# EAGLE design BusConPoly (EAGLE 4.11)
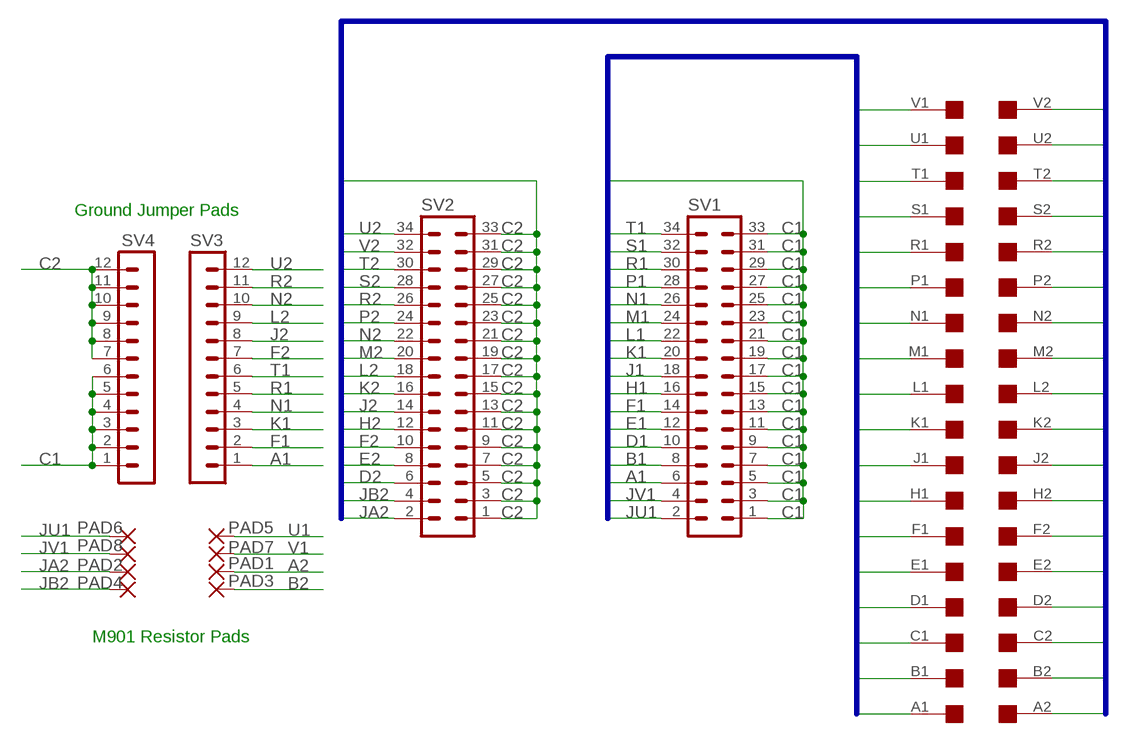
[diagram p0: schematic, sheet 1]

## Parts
PAD1  1,6/0,8  [1,6/0,8]
PAD2  1,6/0,8  [1,6/0,8]
PAD3  1,6/0,8  [1,6/0,8]
PAD4  1,6/0,8  [1,6/0,8]
PAD5  1,6/0,8  [1,6/0,8]
PAD6  1,6/0,8  [1,6/0,8]
PAD7  1,6/0,8  [1,6/0,8]
PAD8  1,6/0,8  [1,6/0,8]
SV1  MA17-2  [MA17-2]
SV2  MA17-2  [MA17-2]
SV3  MA12-1  [MA12-1]
SV4  MA12-1  [MA12-1]
U$4  EDGE-2  [EDGE-CON2]

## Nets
A1: SV1.6 SV3.1 U$4.A1
A2: PAD1.1(P) U$4.A2
B1: SV1.8 U$4.B1
B2: PAD3.1(P) U$4.B2
C1: SV1.1 SV1.3 SV1.5 SV1.7 SV1.9 SV1.11 SV1.13 SV1.15 SV1.17 SV1.19 SV1.21 SV1.23 SV1.25 SV1.27 SV1.29 SV1.31 SV1.33 SV4.1 SV4.2 SV4.3 SV4.4 SV4.5 SV4.6 U$4.C1
C2: SV2.1 SV2.3 SV2.5 SV2.7 SV2.9 SV2.11 SV2.13 SV2.15 SV2.17 SV2.19 SV2.21 SV2.23 SV2.25 SV2.27 SV2.29 SV2.31 SV2.33 SV4.7 SV4.8 SV4.9 SV4.10 SV4.11 SV4.12 U$4.C2
D1: SV1.10 U$4.D1
D2: SV2.6 U$4.D2
E1: SV1.12 U$4.E1
E2: SV2.8 U$4.E2
F1: SV1.14 SV3.2 U$4.F1
F2: SV2.10 SV3.7 U$4.F2
H1: SV1.16 U$4.H1
H2: SV2.12 U$4.H2
J1: SV1.18 U$4.J1
J2: SV2.14 SV3.8 U$4.J2
JA2: PAD2.1(P) SV2.2
JB2: PAD4.1(P) SV2.4
JU1: PAD6.1(P) SV1.2
JV1: PAD8.1(P) SV1.4
K1: SV1.20 SV3.3 U$4.K1
K2: SV2.16 U$4.K2
L1: SV1.22 U$4.L1
L2: SV2.18 SV3.9 U$4.L2
M1: SV1.24 U$4.M1
M2: SV2.20 U$4.M2
N1: SV1.26 SV3.4 U$4.N1
N2: SV2.22 SV3.10 U$4.N2
P1: SV1.28 U$4.P1
P2: SV2.24 U$4.P2
R1: SV1.30 SV3.5 U$4.R1
R2: SV2.26 SV3.11 U$4.R2
S1: SV1.32 U$4.S1
S2: SV2.28 U$4.S2
T1: SV1.34 SV3.6 U$4.T1
T2: SV2.30 U$4.T2
U1: PAD5.1(P) U$4.U1
U2: SV2.34 SV3.12 U$4.U2
V1: PAD7.1(P) U$4.V1
V2: SV2.32 U$4.V2

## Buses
A1,B1,C1,D1,E1,F1,H1,J1,K1,L1,M1,N1,P1,R1,S1,T1,U1,V1
A2,B2,C2,D2,E2,F2,H2,J2,K2,L2,M2,N2,P2,R2,S2,T2,U2,V2

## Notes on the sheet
- Ground Jumper Pads
- M901 Resistor Pads

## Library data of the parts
PAD1-PAD8 = wirepad:1,6/0,8: THROUGH-HOLE PAD
SV1 SV2 = con-lstb:MA17-2: PIN HEADER
SV3 SV4 = con-lstb:MA12-1: PIN HEADER
U$4 = dec-con:EDGE-2: Double-Sided DEC edge connector.

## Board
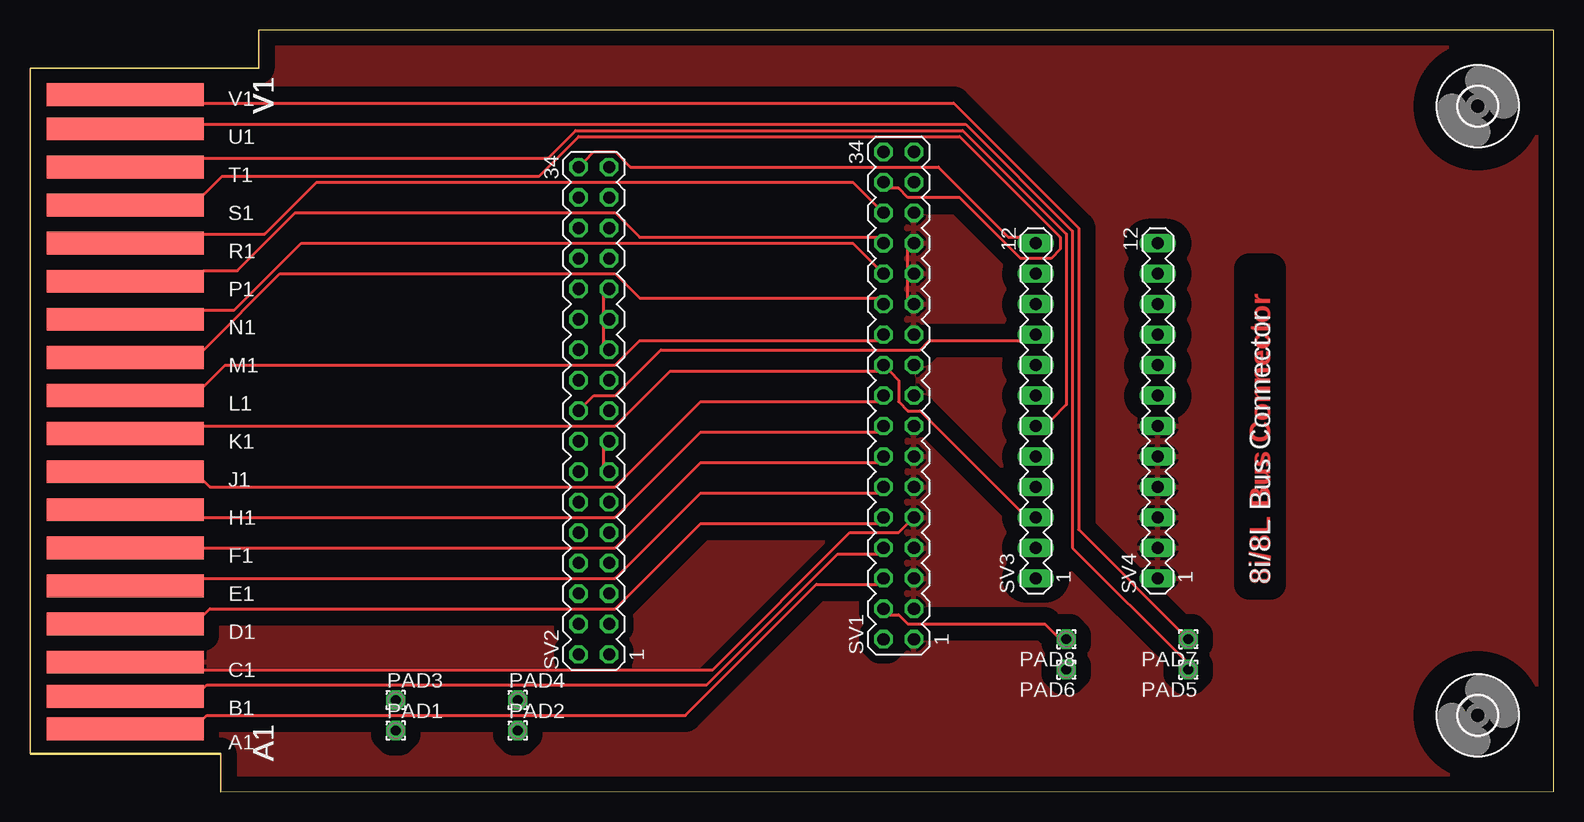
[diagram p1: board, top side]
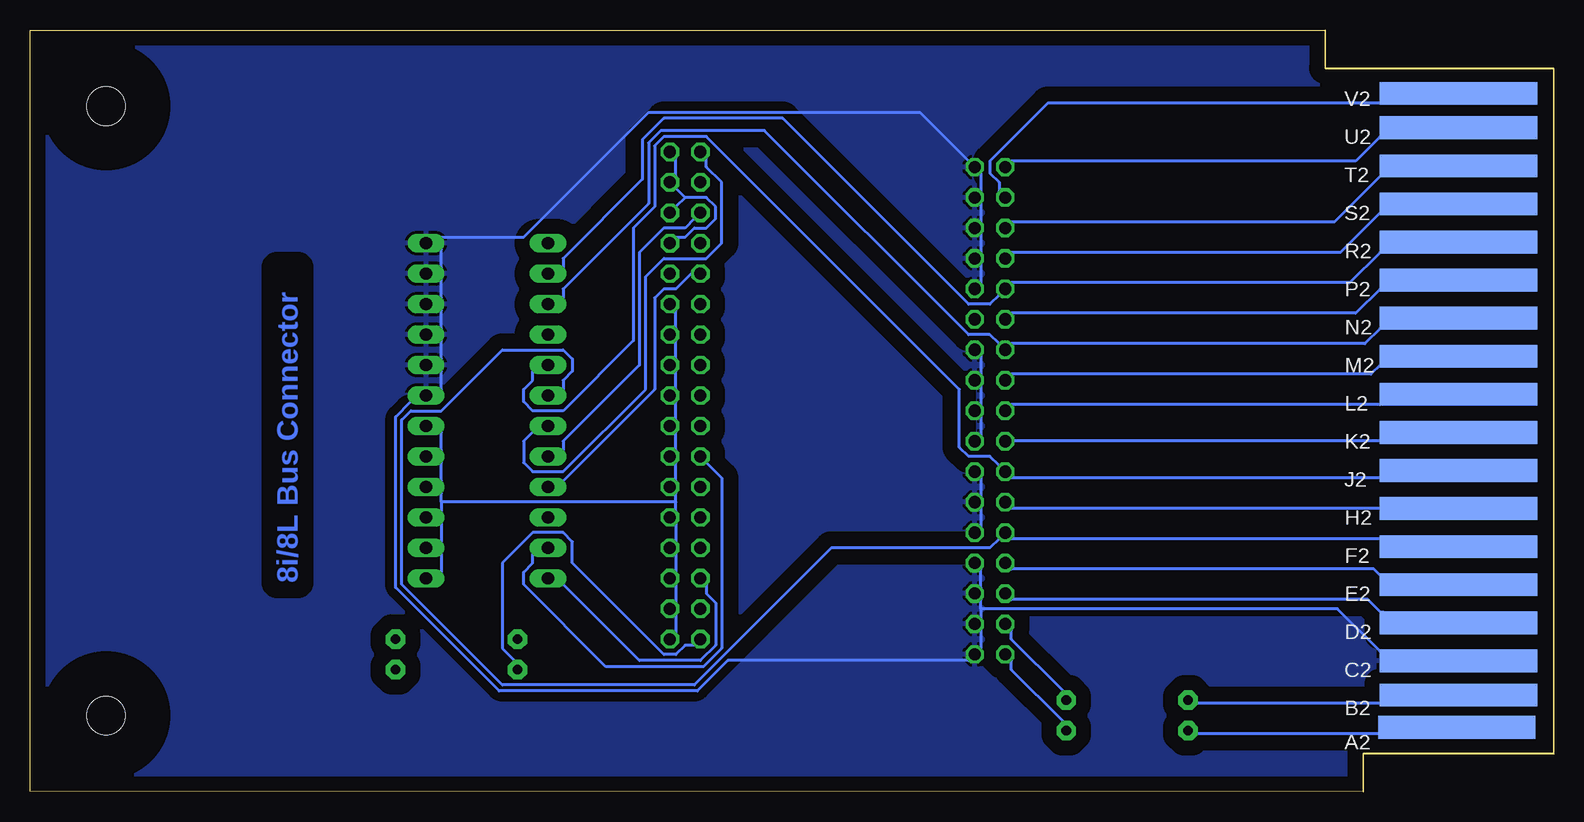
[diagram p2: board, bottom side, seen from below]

Size 126.98 x 63.5 mm. Coordinates in mm from the lower left corner, seen from the top.
Outline: 0.01,3.09 15.88,3.09 15.88,0 126.98,0.04 126.98,63.46 19.05,63.5 19.05,60.29 0.01,60.29 0.01,3.09
Copper layers (1*16): Top 0.035mm / dielectric 1.5mm / Bottom 0.035mm
Design rules "olimex10mil": minimum track width 10mil, minimum drill 24mil, track to track 10mil, track to pad 10mil, pad to pad 10mil, via to via 10mil, smd to smd 10mil, copper to edge 40mil, drill to drill 10mil, minimum pad ring 10mil, minimum via ring 8mil, stop-mask expansion 0mil, vias tented up to drill 0mil, thermal gap 10mil

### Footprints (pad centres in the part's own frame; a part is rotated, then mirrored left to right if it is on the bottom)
1,6/0,8 = drill 0.813 pad 1.6 octagon: 1 0,0
MA17-2 = drill 1.016 octagon: 1 -20.32,-1.27; 2 -20.32,1.27; 3 -17.78,-1.27; 4 -17.78,1.27; 5 -15.24,-1.27; 6 -15.24,1.27; 7 -12.7,-1.27; 8 -12.7,1.27; 9 -10.16,-1.27; 10 -10.16,1.27; 11 -7.62,-1.27; 12 -7.62,1.27; 13 -5.08,-1.27; 14 -5.08,1.27; 15 -2.54,-1.27; 16 -2.54,1.27; 17 0,-1.27; 18 0,1.27; 19 2.54,-1.27; 20 2.54,1.27; 21 5.08,-1.27; 22 5.08,1.27; 23 7.62,-1.27; 24 7.62,1.27; 25 10.16,-1.27; 26 10.16,1.27; 27 12.7,-1.27; 28 12.7,1.27; 29 15.24,-1.27; 30 15.24,1.27; 31 17.78,-1.27; 32 17.78,1.27; 33 20.32,-1.27; 34 20.32,1.27
MA12-1 = drill 1.016 long: 1 -13.97,0; 2 -11.43,0; 3 -8.89,0; 4 -6.35,0; 5 -3.81,0; 6 -1.27,0; 7 1.27,0; 8 3.81,0; 9 6.35,0; 10 8.89,0; 11 11.43,0; 12 13.97,0
3,2 = hole 3.2: 0,0
EDGE-CON2 = smd 13.106 x 1.905: A1 7.938,5.239; B1 7.938,7.938; C1 7.938,10.795; D1 7.938,13.97; E1 7.938,17.145; F1 7.938,20.32; H1 7.938,23.495; J1 7.938,26.67; K1 7.938,29.845; L1 7.938,33.02; M1 7.938,36.195; N1 7.938,39.37; P1 7.938,42.545; R1 7.938,45.72; S1 7.938,48.895; T1 7.938,52.07; U1 7.938,55.245; V1 7.938,58.102 | smd 13.106 x 1.905 bottom: A2 8.096,5.34; B2 7.938,8.039; C2 7.938,10.897; D2 7.938,14.072; E2 7.938,17.247; F2 7.938,20.422; H2 7.938,23.597; J2 7.938,26.772; K2 7.938,29.947; L2 7.938,33.122; M2 7.938,36.297; N2 7.938,39.472; P2 7.938,42.647; R2 7.938,45.822; S2 7.938,48.997; T2 7.938,52.172; U2 7.938,55.347; V2 7.938,58.204

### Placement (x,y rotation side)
PAD1  30.48,5.08 0 top
PAD2  40.64,5.08 0 top
PAD3  30.48,7.62 0 top
PAD4  40.64,7.62 0 top
PAD5  96.52,10.16 180 top
PAD6  86.36,10.16 180 top
PAD7  96.52,12.7 180 top
PAD8  86.36,12.7 180 top
SV1  72.39,33.02 90 top
SV2  46.99,31.75 90 top
SV3  83.82,31.75 90 top
SV4  93.98,31.75 90 top
U$2  [3,2]  120.65,6.35 0 top
U$3  [3,2]  120.65,57.15 0 top
U$4  0,0 0 top

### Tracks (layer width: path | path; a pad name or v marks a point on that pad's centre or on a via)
A1
  Top 0.254: SV1.6 70.61,17.27 65.53,17.27 54.61,6.35 14.73,6.35 14.48,6.1 U$4.A1
  Bottom 0.254: SV1.6 70.61,17.27 70.61,16.51 69.85,15.75 69.85,12.19 71.12,10.92 76.2,10.92 82.55,17.27 SV3.1
A2
  Bottom 0.254: PAD1.1 29.72,4.83 14.48,4.83 U$4.A2
B1
  Top 0.254: SV1.8 70.61,19.81 67.31,19.81 56.39,8.89 14.73,8.89 14.48,8.64 U$4.B1
B2
  Bottom 0.254: PAD3.1 29.72,7.37 14.48,7.37 U$4.B2
C1
  Top 0.254: SV1.23 73.15,41.15 73.15,42.67 SV1.25 73.15,43.69 73.15,45.21 SV1.27 | U$4.C1 14.48,10.16 56.9,10.16 68.33,21.59 72.39,21.59 73.15,22.35 SV1.9
  Bottom 0.254: SV4.1 92.71,18.29 92.71,19.81 SV4.2 92.71,20.83 92.71,22.35 SV4.3 92.71,23.37 92.71,24.13 | 92.71,24.13 92.71,24.89 SV4.4 92.71,25.91 92.71,27.43 SV4.5 92.71,28.45 92.71,29.97 SV4.6 | 72.39,49.53 70.61,49.53 69.85,48.77 69.85,47.75 70.61,46.99 71.63,46.99 72.39,46.23 73.15,46.23 SV1.27 | 72.39,49.53 73.15,50.29 SV1.31 73.15,51.31 73.15,52.83 SV1.33 | 72.39,49.53 73.15,48.77 SV1.29 | SV1.1 73.15,13.21 73.15,14.73 SV1.3 73.15,15.75 73.15,17.27 SV1.5 73.15,18.29 73.15,19.81 SV1.7 73.15,20.83 73.15,22.35 SV1.9 73.15,23.37 73.15,24.13 | 73.15,24.13 73.15,24.89 SV1.11 73.15,25.91 73.15,27.43 SV1.13 73.15,28.45 73.15,29.97 SV1.15 73.15,30.99 73.15,32.51 SV1.17 73.15,33.53 73.15,35.05 SV1.19 73.15,36.07 73.15,37.59 SV1.21 73.15,38.61 73.15,40.13 SV1.23 | 73.15,24.13 92.71,24.13
  pour Top (isolate 1.27): 0,59.69 19.05,59.69 19.05,63.5 127,63.5 127,0 16.51,0 16.51,2.54 16.51,3.81 0,3.81
C2
  Top 0.254: SV2.21 47.75,37.34 47.75,38.86 SV2.23 47.75,39.88 47.75,41.4 SV2.25 | SV2.13 47.75,27.18 47.75,28.7 SV2.15
  Bottom 0.254: 47.75,15.24 47.75,14.48 SV2.3 47.75,13.46 47.75,11.94 SV2.1 48.77,10.92 68.83,10.92 71.37,8.38 87.88,8.38 96.52,17.02 96.52,31.24 95.25,32.51 SV4.7 92.71,33.53 92.71,35.05 SV4.8 92.71,36.07 92.71,37.59 SV4.9 92.71,38.61 92.71,40.13 SV4.10 92.71,41.15 92.71,42.67 SV4.11 92.71,43.69 92.71,45.21 SV4.12 92.71,46.23 85.85,46.23 75.44,56.64 52.83,56.64 48.77,52.58 SV2.33 47.75,51.56 47.75,50.04 SV2.31 47.75,49.02 47.75,47.5 SV2.29 47.75,46.48 47.75,44.96 SV2.27 47.75,43.94 47.75,42.42 SV2.25 | 47.75,15.24 47.75,16 SV2.5 47.75,17.02 47.75,18.54 SV2.7 | 47.75,15.24 18.03,15.24 14.48,11.68 U$4.C2 | SV2.9 47.75,22.1 47.75,23.62 SV2.11 47.75,24.64 47.75,26.16 SV2.13 | SV2.15 47.75,29.72 47.75,31.24 SV2.17 47.75,32.26 47.75,33.78 SV2.19 47.75,34.8 47.75,36.32 SV2.21
  pour Bottom (isolate 1.27): 0,59.69 19.05,59.69 19.05,63.5 127,63.5 127,0 16.51,0 16.51,2.54 16.51,3.81 0,3.81
D1
  Top 0.254: SV1.10 70.61,22.35 55.88,22.35 48.77,15.24 14.99,15.24 14.48,14.73 U$4.D1
D2
  Bottom 0.254: SV2.6 45.21,16 15.49,16 14.48,14.99 U$4.D2
E1
  Top 0.254: SV1.12 70.61,24.89 55.88,24.89 48.77,17.78 14.48,17.78 U$4.E1
E2
  Bottom 0.254: SV2.8 45.21,18.54 14.99,18.54 14.48,18.03 U$4.E2
F1
  Top 0.254: SV1.14 70.61,27.43 55.88,27.43 48.77,20.32 14.48,20.32 U$4.F1
  Bottom 0.254: SV3.2 85.09,19.81 85.09,19.05 85.85,18.29 85.85,17.27 78.99,10.41 70.87,10.41 69.34,11.94 69.34,26.16 70.61,27.43 SV1.14
F2
  Bottom 0.254: U$4.F2 14.48,21.08 45.21,21.08 SV2.10 46.23,21.08 46.99,20.32 60.2,20.32 71.63,8.89 87.63,8.89 96.01,17.27 96.01,30.99 95.25,31.75 92.71,31.75 87.63,36.83 82.55,36.83 81.79,36.07 81.79,35.05 82.55,34.29 82.55,33.53 SV3.7
H1
  Top 0.254: SV1.16 70.61,29.97 55.88,29.97 48.77,22.86 14.48,22.86 U$4.H1
H2
  Bottom 0.254: SV2.12 45.21,23.62 14.48,23.62 U$4.H2
J1
  Top 0.254: SV1.18 70.61,32.51 55.88,32.51 48.77,25.4 14.99,25.4 14.48,25.91 U$4.J1
J2
  Bottom 0.254: U$4.J2 14.48,26.16 45.21,26.16 SV2.14 46.23,27.18 46.99,27.94 48.77,27.94 49.53,28.7 49.53,33.53 70.61,54.61 74.17,54.61 74.93,53.85 74.93,48.77 76.71,46.99 76.71,37.59 82.55,31.75 85.09,31.75 85.85,32.51 85.85,33.53 85.09,34.29 85.09,35.05 SV3.8
JA2
  Bottom 0.254: SV2.2 45.21,10.92 45.21,10.16 40.89,5.84 PAD2.1
JB2
  Bottom 0.254: SV2.4 45.21,13.46 45.21,12.7 40.89,8.38 PAD4.1
JU1
  Bottom 0.254: SV1.2 71.63,12.19 72.39,12.19 73.15,11.43 74.17,11.43 81.79,19.05 81.79,20.83 82.55,21.59 85.09,21.59 87.63,19.05 87.63,11.94 86.61,10.92 PAD6.1
JV1
  Top 0.254: SV1.4 71.63,14.73 72.39,14.73 73.15,13.97 84.58,13.97 85.6,12.95 PAD8.1
K1
  Top 0.254: SV3.3 82.55,23.37 74.17,31.75 73.15,31.75 72.39,32.51 72.39,34.29 71.63,35.05 SV1.20 70.61,35.05 53.34,35.05 48.77,30.48 14.48,30.48 U$4.K1
K2
  Bottom 0.254: SV2.16 45.21,29.21 14.48,29.21 U$4.K2
L1
  Top 0.254: SV1.22 70.61,37.59 50.8,37.59 48.77,35.56 16.26,35.56 14.48,33.78 U$4.L1
L2
  Top 0.254: SV3.9 82.55,37.59 74.93,37.59 74.17,36.83 52.58,36.83 48.77,33.02 46.99,33.02 46.23,32.26 SV2.18
  Bottom 0.254: SV2.18 45.21,32.26 14.48,32.26 U$4.L2
M1
  Top 0.254: SV1.24 70.61,41.15 50.8,41.15 48.77,43.18 20.83,43.18 14.48,36.83 U$4.M1
M2
  Bottom 0.254: SV2.20 45.21,34.8 15.24,34.8 14.48,35.56 U$4.M2
N1
  Top 0.254: U$4.N1 14.48,40.13 17.02,40.13 22.61,45.72 68.58,45.72 70.61,43.69 SV1.26
  Bottom 0.254: SV3.4 82.55,25.91 74.93,33.53 74.93,41.15 74.17,41.91 73.15,41.91 71.63,43.43 SV1.26
N2
  Bottom 0.254: U$4.N2 14.48,38.61 15.75,37.34 45.21,37.34 SV2.22 46.23,37.34 46.99,38.1 48.77,38.1 65.79,55.12 74.42,55.12 75.44,54.1 75.44,49.02 82.55,41.91 82.55,41.15 SV3.10
P1
  Top 0.254: SV1.28 70.61,46.23 50.8,46.23 48.77,48.26 22.1,48.26 17.27,43.43 14.48,43.43 U$4.P1
P2
  Bottom 0.254: SV2.24 45.21,39.88 16.51,39.88 14.48,41.91 U$4.P2
R1
  Top 0.254: U$4.R1 14.48,46.48 19.56,46.48 23.88,50.8 68.58,50.8 70.61,48.77 SV1.30
  Bottom 0.254: SV3.5 82.55,28.45 82.55,29.21 76.2,35.56 76.2,44.96 74.17,46.99 72.39,46.99 71.63,47.75 SV1.30
R2
  Bottom 0.254: U$4.R2 14.48,44.96 17.02,42.42 45.21,42.42 SV2.26 46.23,41.4 46.99,40.64 48.77,40.64 64.26,56.13 74.17,56.13 75.95,54.36 75.95,51.05 82.55,44.45 82.55,43.69 SV3.11
S1
  Top 0.254: SV1.32 71.63,50.29 72.39,50.29 73.15,49.53 77.47,49.53 82.55,44.45 85.09,44.45 85.85,45.21 85.85,46.23 77.47,54.61 45.72,54.61 42.42,51.31 16,51.31 14.48,49.78 U$4.S1
S2
  Bottom 0.254: SV2.28 45.21,44.96 17.78,44.96 14.48,48.26 U$4.S2
T1
  Top 0.254: U$4.T1 14.48,52.83 43.18,52.83 45.47,55.12 77.72,55.12 86.36,46.48 86.36,32.26 85.09,30.99 SV3.6
  Bottom 0.254: SV1.34 70.61,52.83 70.61,52.07 69.34,50.8 69.34,45.72 70.61,44.45 74.17,44.45 75.69,42.93 75.69,33.53 82.55,26.67 85.09,26.67 85.85,27.43 85.85,29.21 85.09,29.97 SV3.6
T2
  Bottom 0.254: SV2.30 45.21,47.5 18.29,47.5 14.48,51.31 U$4.T2
U1
  Top 0.254: PAD5.1 96.27,10.92 86.87,20.32 86.87,46.74 77.98,55.63 14.48,55.63 U$4.U1
U2
  Top 0.254: SV3.12 82.55,46.23 81.53,46.23 75.69,52.07 50.04,52.07 48.77,53.34 46.99,53.34 46.23,52.58 SV2.34
  Bottom 0.254: SV2.34 45.21,52.58 16.51,52.58 14.48,54.61 U$4.U2
V1
  Top 0.254: PAD7.1 96.01,13.21 87.38,21.84 87.38,46.99 76.96,57.4 14.48,57.4 U$4.V1
V2
  Bottom 0.254: SV2.32 46.23,50.04 46.23,50.8 46.99,51.56 46.99,52.58 42.16,57.4 14.48,57.4 U$4.V2

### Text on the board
Top: 8i/8L Bus Connector
Bottom: 8i/8L Bus Connector
tPlace: 8i/8L Bus Connector
tNames: V1 | V1 | V1 | V1 | V1 | V1 | V1 | V1 | V1 | V1 | V1 | V1 | V1 | V1 | V1 | V1 | V1 | V1 | V1 | V1 | V1 | V1 | V1 | V1 | V1 | V1 | V1 | V1 | V1 | V1 | V1 | V1 | A1 | A1 | A1 | A1 | A1 | A1 | A1 | A1 | A1 | A1 | A1 | A1 | A1 | A1 | A1 | A1 | A1 | A1 | A1 | A1 | A1 | A1 | A1 | A1 | A1 | A1 | A1 | A1 | A1 | A1 | A1 | A1
tValues: Jumper unless M901 | M90x/W0x1 - always used | M901/M903/M904 - Use both | M901 | 10ohm | M901 | 10ohm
